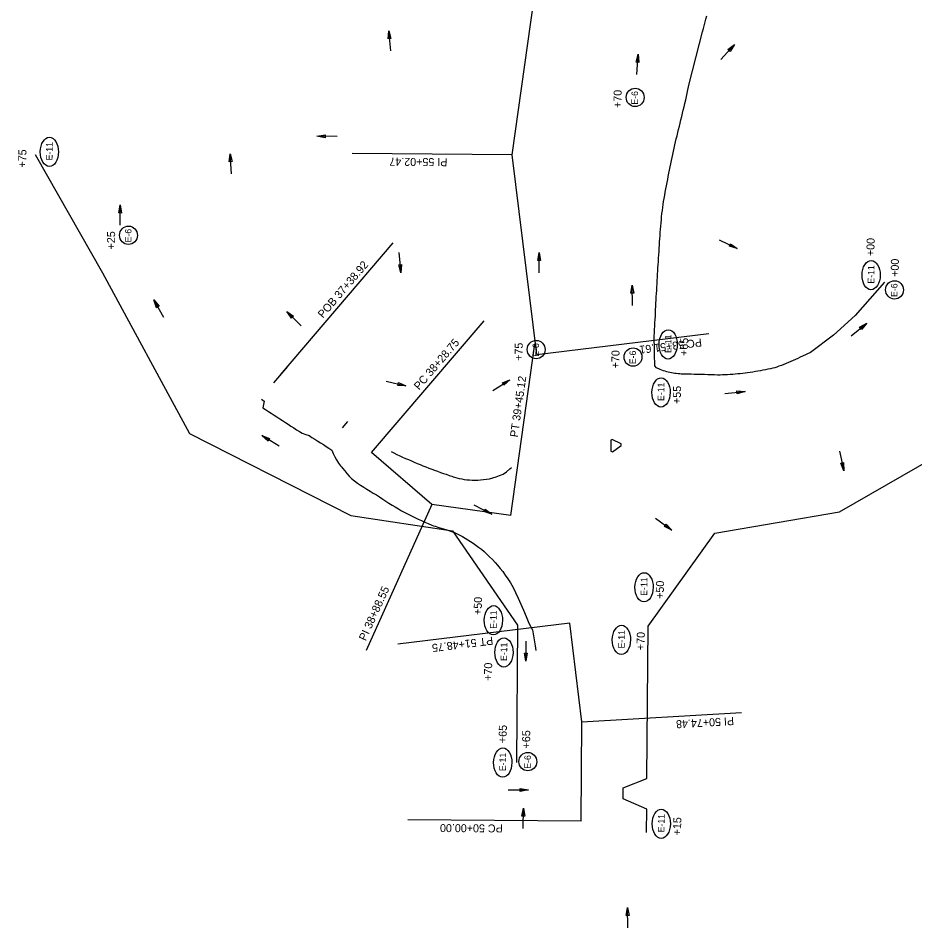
# Model space of a CAD drawing. Extents: x 1312891 to 1314734, y 2088044 to 2090982.
# Drawn here: x 1313567 to 1314240, y 2088044 to 2088726 of the extents above; entities that cross this region are included whole.
import ezdxf

# ---------------------------------------------------------------- set-up
doc = ezdxf.new("R2010")
doc.units = 0
for name, color, linetype in [('43', 7, 'Continuous'), ('44', 7, 'Continuous'), ('Level 1', 7, 'Continuous'), ('Level 44', 7, 'Continuous'), ('R_Horz Alg Annot_Detour', 7, 'Continuous'), ('R_Horz Alg Stationing_Detour', 7, 'Continuous'), ('R_Proposed Const Limits', 7, 'Continuous'), ('R_Proposed Road', 7, 'Continuous')]:
    doc.layers.add(name, color=color, linetype=linetype)

msp = doc.modelspace()

# ---------------------------------------------------------------- linework, layer by layer
at = {"layer": '43'}
for p, q in [((1313844.54, 2088710.17), (1313844.96, 2088716.32)), ((1313844.96, 2088716.32), (1313846.68, 2088710.4)), ((1313846.68, 2088710.4), (1313844.54, 2088710.17)), ((1314099.44, 2088702.13), (1314104.37, 2088705.84)), ((1314101.01, 2088700.67), (1314099.44, 2088702.13)), ((1314104.37, 2088705.84), (1314101.01, 2088700.67)), ((1314030.55, 2088692.66), (1314032.03, 2088698.65)), ((1314032.03, 2088698.65), (1314032.69, 2088692.51)), ((1314032.69, 2088692.51), (1314030.55, 2088692.66)), ((1313791.13, 2088637.22), (1313797.22, 2088638.24)), ((1313797.2, 2088636.1), (1313791.13, 2088637.22)), ((1313797.22, 2088638.24), (1313797.2, 2088636.1)), ((1313725.37, 2088617.96), (1313725.96, 2088624.1)), ((1313725.96, 2088624.1), (1313727.51, 2088618.13)), ((1313727.51, 2088618.13), (1313725.37, 2088617.96)), ((1313642.43, 2088579.66), (1313643.56, 2088585.72)), ((1313643.56, 2088585.72), (1313644.58, 2088579.64)), ((1313644.58, 2088579.64), (1313642.43, 2088579.66)), ((1314100.5, 2088554.7), (1314101.44, 2088556.63)), ((1314106.44, 2088553.02), (1314100.5, 2088554.7)), ((1314101.44, 2088556.63), (1314106.44, 2088553.02)), ((1313956.79, 2088543.99), (1313957.89, 2088550.06)), ((1313958.94, 2088543.98), (1313956.79, 2088543.99)), ((1313957.89, 2088550.06), (1313958.94, 2088543.98)), ((1313852.45, 2088540.8), (1313854.58, 2088541.03)), ((1313854.15, 2088534.87), (1313852.45, 2088540.8)), ((1313854.58, 2088541.03), (1313854.15, 2088534.87)), ((1314026.65, 2088519.5), (1314027.71, 2088525.57)), ((1314027.71, 2088525.57), (1314028.8, 2088519.5)), ((1314028.8, 2088519.5), (1314026.65, 2088519.5)), ((1313668.76, 2088514.45), (1313672.69, 2088509.69)), ((1313670.82, 2088508.63), (1313668.76, 2088514.45)), ((1313672.69, 2088509.69), (1313670.82, 2088508.63)), ((1313768.49, 2088505.76), (1313773.58, 2088502.28)), ((1313772.08, 2088500.74), (1313768.49, 2088505.76)), ((1313773.58, 2088502.28), (1313772.08, 2088500.74)), ((1314198.21, 2088494.08), (1314203.6, 2088497.08)), ((1314203.6, 2088497.08), (1314199.57, 2088492.41)), ((1314199.57, 2088492.41), (1314198.21, 2088494.08)), ((1313851.74, 2088450.37), (1313852.22, 2088452.46)), ((1313857.9, 2088450.05), (1313851.74, 2088450.37)), ((1313852.22, 2088452.46), (1313857.9, 2088450.05)), ((1313930.23, 2088452.33), (1313935.95, 2088454.65)), ((1313931.37, 2088450.51), (1313930.23, 2088452.33)), ((1313935.95, 2088454.65), (1313931.37, 2088450.51)), ((1314106.41, 2088444.08), (1314106.19, 2088446.22)), ((1314106.19, 2088446.22), (1314112.34, 2088445.77)), ((1314112.34, 2088445.77), (1314106.41, 2088444.08)), ((1313749.84, 2088412.78), (1313755.57, 2088410.48)), ((1313754.44, 2088408.66), (1313749.84, 2088412.78)), ((1313755.57, 2088410.48), (1313754.44, 2088408.66)), ((1314184.04, 2088392.04), (1314186.13, 2088392.52)), ((1314186.46, 2088386.36), (1314184.04, 2088392.04)), ((1314186.13, 2088392.52), (1314186.46, 2088386.36)), ((1313916.37, 2088355.83), (1313917.36, 2088357.73)), ((1313922.26, 2088353.98), (1313916.37, 2088355.83)), ((1313917.36, 2088357.73), (1313922.26, 2088353.98)), ((1314051.87, 2088344.67), (1314053.14, 2088346.4)), ((1314053.14, 2088346.4), (1314057.4, 2088341.93)), ((1314057.4, 2088341.93), (1314051.87, 2088344.67)), ((1313947.77, 2088243.59), (1313946.72, 2088249.67)), ((1313946.72, 2088249.67), (1313948.87, 2088249.66)), ((1313948.87, 2088249.66), (1313947.77, 2088243.59)), ((1313943.69, 2088146.06), (1313943.69, 2088148.2)), ((1313943.69, 2088148.2), (1313949.76, 2088147.11)), ((1313949.76, 2088147.11), (1313943.69, 2088146.06)), ((1313944.89, 2088127.46), (1313946.01, 2088133.52)), ((1313946.01, 2088133.52), (1313947.03, 2088127.44)), ((1313947.03, 2088127.44), (1313944.89, 2088127.46)), ((1314023.16, 2088052.89), (1314024.22, 2088058.97)), ((1314024.22, 2088058.97), (1314025.31, 2088052.89)), ((1314025.31, 2088052.89), (1314023.16, 2088052.89))]:
    msp.add_line(p, q, dxfattribs=at)
for points in [[(1313846.58, 2088701.22), (1313844.96, 2088716.32)], [(1314094, 2088694.74), (1314104.37, 2088705.84)], [(1314030.99, 2088683.49), (1314032.03, 2088698.65)], [(1313806.32, 2088637.09), (1313791.13, 2088637.22)], [(1313727.17, 2088608.96), (1313725.96, 2088624.1)], [(1313643.43, 2088570.53), (1313643.56, 2088585.72)], [(1314092.77, 2088559.63), (1314106.44, 2088553.02)], [(1313852.56, 2088549.98), (1313854.15, 2088534.87)], [(1313957.81, 2088534.87), (1313957.89, 2088550.06)], [(1314027.75, 2088510.39), (1314027.71, 2088525.57)], [(1313676.24, 2088501.23), (1313668.76, 2088514.45)], [(1313779.35, 2088495.14), (1313768.49, 2088505.76)], [(1314191.83, 2088487.48), (1314203.6, 2088497.08)], [(1313843.1, 2088453.46), (1313857.9, 2088450.05)], [(1313923.08, 2088446.58), (1313935.95, 2088454.65)], [(1314097.23, 2088444.22), (1314112.34, 2088445.77)], [(1313762.75, 2088404.77), (1313749.84, 2088412.78)], [(1314183.02, 2088401.16), (1314186.46, 2088386.36)], [(1313908.78, 2088360.98), (1313922.26, 2088353.98)], [(1314045.17, 2088350.94), (1314057.4, 2088341.93)], [(1313947.82, 2088258.78), (1313947.77, 2088243.59)], [(1313934.58, 2088147.16), (1313949.76, 2088147.11)], [(1313945.88, 2088118.33), (1313946.01, 2088133.52)], [(1314024.26, 2088043.78), (1314024.22, 2088058.97)]]:
    msp.add_lwpolyline(points, dxfattribs=at)
at = {"layer": 'Level 1'}
for centre, major_axis, ratio in [((1314029.82, 2088666.31), (-0.05, -6.88), 0.97521), ((1313590.41, 2088625.46), (0.1, 10.96), 0.622952), ((1313649.76, 2088562.93), (-0.05, -6.88), 0.97521), ((1314206.86, 2088533.08), (0.1, 10.96), 0.622952), ((1314224.38, 2088522.03), (-0.05, -6.88), 0.97521), ((1314054.62, 2088481.15), (0.1, 10.96), 0.622952), ((1313955.62, 2088477.26), (-0.05, -6.88), 0.97521), ((1314028.25, 2088471.64), (-0.05, -6.88), 0.97521), ((1314049.28, 2088445.12), (0.1, 10.96), 0.622952), ((1314036.53, 2088299.05), (0.1, 10.96), 0.622952), ((1313923.53, 2088274.32), (0.1, 10.96), 0.622952), ((1314019.54, 2088259.61), (0.1, 10.96), 0.622952), ((1313931.43, 2088250.21), (0.1, 10.96), 0.622952), ((1313930.52, 2088167.62), (0.1, 10.96), 0.622952), ((1313949.37, 2088168.37), (-0.05, -6.88), 0.97521), ((1314049.47, 2088121.73), (0.1, 10.96), 0.622952)]:
    msp.add_ellipse(centre, major_axis=major_axis, ratio=ratio, dxfattribs=at)
at = {"layer": 'Level 44'}
for points in [[(1314044.05, 2088484.84), (1314044.18, 2088487.34), (1314044.31, 2088489.83), (1314044.45, 2088492.33), (1314044.58, 2088494.82), (1314044.72, 2088497.32), (1314044.85, 2088499.83), (1314044.99, 2088502.46), (1314045.06, 2088505.03), (1314045.14, 2088507.34), (1314045.26, 2088509.63), (1314045.4, 2088512.02), (1314045.54, 2088514.42), (1314045.69, 2088516.83), (1314045.84, 2088519.23), (1314046, 2088521.63), (1314046.17, 2088524.13), (1314046.3, 2088526.66), (1314046.4, 2088529.11), (1314046.51, 2088531.51), (1314046.63, 2088533.9), (1314046.75, 2088536.2), (1314046.91, 2088538.51), (1314047.09, 2088540.91), (1314047.27, 2088543.31), (1314047.46, 2088545.73), (1314047.65, 2088548.26), (1314047.79, 2088550.78), (1314047.92, 2088553.18), (1314048.06, 2088555.58), (1314048.21, 2088557.98), (1314048.35, 2088560.38), (1314048.5, 2088562.78), (1314048.65, 2088565.11), (1314048.84, 2088567.41), (1314049.05, 2088569.77), (1314049.26, 2088572.15), (1314049.49, 2088574.53), (1314049.65, 2088576.15), (1314049.72, 2088576.83), (1314049.98, 2088579.23), (1314050.25, 2088581.62), (1314050.5, 2088583.9), (1314050.78, 2088585.97), (1314051.17, 2088588.14), (1314051.61, 2088590.51), (1314052.07, 2088592.96), (1314052.47, 2088595.35), (1314052.91, 2088597.66), (1314053.35, 2088600.02), (1314053.81, 2088602.39), (1314054.27, 2088604.75), (1314054.73, 2088607.12), (1314055.2, 2088609.48), (1314055.68, 2088611.84), (1314056.16, 2088614.2), (1314056.65, 2088616.55), (1314057.14, 2088618.91), (1314057.64, 2088621.26), (1314058.14, 2088623.61), (1314058.65, 2088625.97), (1314059.16, 2088628.31), (1314059.68, 2088630.66), (1314060.2, 2088632.97), (1314060.73, 2088635.23), (1314061.3, 2088637.53), (1314061.9, 2088639.94), (1314062.46, 2088642.34), (1314063.02, 2088644.69), (1314063.6, 2088647.08), (1314064.18, 2088649.54), (1314064.76, 2088651.99), (1314065.33, 2088654.36), (1314065.93, 2088656.73), (1314066.56, 2088659.16), (1314067.22, 2088661.75), (1314067.83, 2088664.45), (1314068.35, 2088667.01), (1314068.85, 2088669.47), (1314069.35, 2088671.92), (1314069.83, 2088674.29), (1314070.32, 2088676.49), (1314080.43, 2088715.42), (1314081.07, 2088717.84), (1314082.98, 2088725.07), (1314083.64, 2088727.39)], [(1313579.68, 2088623.4), (1313630.18, 2088534.77), (1313695.42, 2088414.4), (1313816.45, 2088352.89), (1313892.77, 2088341.33), (1313941.6, 2088270.63)], [(1314216.93, 2088527.81), (1314194.89, 2088502.8), (1314178.67, 2088487.98), (1314161.35, 2088475.05)], [(1314044.71, 2088465.07), (1314044.68, 2088465.78), (1314044.57, 2088468.29), (1314044.46, 2088470.8), (1314044.36, 2088473.24), (1314044.28, 2088475.55), (1314044.27, 2088477.95), (1314044.24, 2088480.66), (1314044.12, 2088483.21), (1314044.05, 2088484.84)], [(1314161.35, 2088475.05), (1314155.45, 2088472.26), (1314153.71, 2088471.46), (1314151.88, 2088470.64), (1314150.08, 2088469.82), (1314148.35, 2088469.05), (1314146.61, 2088468.29), (1314144.85, 2088467.55), (1314143.08, 2088466.83), (1314141.31, 2088466.12), (1314139.52, 2088465.43), (1314137.74, 2088464.77), (1314136.05, 2088464.15), (1314134.6, 2088463.68), (1314133.11, 2088463.3), (1314131.33, 2088462.9), (1314129.45, 2088462.49), (1314127.57, 2088462.1), (1314125.69, 2088461.73), (1314123.81, 2088461.38), (1314121.92, 2088461.04), (1314120.04, 2088460.72), (1314118.1, 2088460.41), (1314116.15, 2088460.1), (1314114.24, 2088459.81), (1314112.42, 2088459.55), (1314110.61, 2088459.33), (1314108.74, 2088459.13), (1314106.85, 2088458.95), (1314104.95, 2088458.79), (1314103.04, 2088458.64), (1314101.14, 2088458.52), (1314099.23, 2088458.41), (1314097.32, 2088458.32), (1314095.41, 2088458.24), (1314093.51, 2088458.19), (1314091.56, 2088458.16), (1314089.34, 2088458.22), (1314086.9, 2088458.31), (1314084.39, 2088458.4), (1314081.88, 2088458.49), (1314079.37, 2088458.58), (1314076.62, 2088458.68), (1314074.07, 2088458.64), (1314071.76, 2088458.7), (1314069.23, 2088458.76), (1314066.86, 2088458.8), (1314065.57, 2088458.81), (1314064.48, 2088458.86), (1314063.32, 2088458.95), (1314062, 2088459.08), (1314060.73, 2088459.2), (1314059.59, 2088459.35), (1314058.31, 2088459.56), (1314057.03, 2088459.77), (1314055.87, 2088460), (1314054.69, 2088460.28), (1314053.49, 2088460.6), (1314052.28, 2088460.97), (1314051.05, 2088461.38), (1314049.81, 2088461.85), (1314048.54, 2088462.38), (1314045.97, 2088463.54)], [(1314039.59, 2088269.85), (1314089.53, 2088339.75), (1314183.09, 2088355.58), (1314300.77, 2088423.05), (1314312.71, 2088465.89)], [(1314045.97, 2088463.54), (1314044.71, 2088465.07)], [(1313941.6, 2088270.63), (1313940.78, 2088167.59)], [(1314038.36, 2088115.33), (1314038.5, 2088132.66), (1314020.79, 2088140.53), (1314020.9, 2088148.61), (1314038.68, 2088155.68), (1314039.59, 2088269.85)]]:
    msp.add_lwpolyline(points, dxfattribs=at)
at = {"layer": 'R_Horz Alg Annot_Detour'}
for points in [[(1313956.03, 2088473.54), (1313937.64, 2088623.28), (1313958.64, 2088772.67)], [(1313937.64, 2088623.28), (1313817.65, 2088624.33)], [(1313763.74, 2088458.44), (1313848.31, 2088557.17)], [(1313831.96, 2088400), (1313916.53, 2088498.73)], [(1313956.03, 2088473.54), (1314085.06, 2088489.38)], [(1313936.6, 2088352.77), (1313954.7, 2088481.51)], [(1313936.6, 2088352.77), (1313877.38, 2088361.1), (1313831.96, 2088400)], [(1313877.38, 2088361.1), (1313828.01, 2088251.72)], [(1313980.75, 2088272.19), (1313851.72, 2088256.35)], [(1313989.26, 2088123.79), (1313989.83, 2088198.27), (1313980.75, 2088272.19)], [(1313989.83, 2088198.27), (1314109.63, 2088205.14)], [(1313989.26, 2088123.79), (1313859.26, 2088124.78)]]:
    msp.add_lwpolyline(points, dxfattribs=at)
at = {"layer": 'R_Horz Alg Stationing_Detour'}
for points in [[(1313768.94, 2088464.52), (1313758.53, 2088452.37)], [(1313768.94, 2088464.52), (1313758.53, 2088452.37)], [(1313814.03, 2088423.26), (1313810.13, 2088418.71)]]:
    msp.add_lwpolyline(points, dxfattribs=at)
at = {"layer": 'R_Proposed Const Limits'}
for points in [[(1313749.43, 2088440.08), (1313751.53, 2088438.69), (1313750.54, 2088433.69), (1313752.65, 2088432.31), (1313754.77, 2088430.94), (1313756.89, 2088429.57), (1313759.01, 2088428.2), (1313761.13, 2088426.83), (1313763.23, 2088425.45), (1313765.33, 2088424.06), (1313767.43, 2088422.66), (1313769.53, 2088421.27), (1313771.63, 2088419.88), (1313773.75, 2088418.51), (1313775.87, 2088417.14), (1313777.99, 2088415.77), (1313780.18, 2088414.49), (1313782.7, 2088413.59), (1313785.29, 2088412.77), (1313787.43, 2088411.42), (1313789.56, 2088410.07), (1313791.69, 2088408.71), (1313793.81, 2088407.35), (1313795.94, 2088405.98), (1313798.06, 2088404.62), (1313800.18, 2088403.25), (1313802.2, 2088401.77)], [(1313802.2, 2088401.77), (1313803.43, 2088399.36), (1313804.68, 2088396.97), (1313805.93, 2088394.59), (1313807.19, 2088392.21), (1313808.74, 2088390.18), (1313809.82, 2088389.05), (1313809.79, 2088389), (1313810.4, 2088388.28), (1313811.99, 2088386.3), (1313813.58, 2088384.31), (1313815.28, 2088382.45), (1313817.13, 2088380.54), (1313819.29, 2088378.75), (1313821.51, 2088377.05), (1313823.86, 2088375.51), (1313826.22, 2088374.01), (1313828.61, 2088372.53), (1313831.01, 2088371.09), (1313833.42, 2088369.69), (1313835.85, 2088368.31), (1313838.16, 2088366.76), (1313840.46, 2088365.21), (1313842.78, 2088363.68), (1313845.12, 2088362.18), (1313847.48, 2088360.71), (1313849.85, 2088359.26), (1313852.24, 2088357.84), (1313854.67, 2088356.49), (1313857.1, 2088355.14), (1313859.55, 2088353.82), (1313862.01, 2088352.53), (1313864.49, 2088351.28), (1313867.03, 2088350.14), (1313869.57, 2088349.02), (1313872.13, 2088347.93), (1313874.68, 2088346.82), (1313877.23, 2088345.74), (1313878.69, 2088345.19), (1313879.85, 2088344.79), (1313882.48, 2088343.91), (1313885.13, 2088343.07), (1313887.78, 2088342.26), (1313890.04, 2088341.58), (1313892.15, 2088340.89), (1313894.21, 2088340.03), (1313896.25, 2088339.09), (1313898.28, 2088338.09), (1313900.3, 2088337.03), (1313902.3, 2088335.89), (1313904.31, 2088334.69), (1313906.31, 2088333.41), (1313908.34, 2088332.08), (1313910.38, 2088330.69), (1313912.44, 2088329.2), (1313914.49, 2088327.59), (1313916.54, 2088325.84), (1313918.61, 2088323.97), (1313920.7, 2088321.97), (1313922.81, 2088319.8), (1313924.75, 2088317.73), (1313926.68, 2088315.55), (1313928.61, 2088313.24), (1313930.53, 2088310.78), (1313932.45, 2088308.15), (1313934.38, 2088305.32), (1313936.3, 2088302.28), (1313938.23, 2088298.96), (1313940.18, 2088295.24), (1313942.21, 2088290.98), (1313944.12, 2088286.52), (1313946.04, 2088281.89), (1313947.98, 2088277.09), (1313950.03, 2088272.11), (1313952.72, 2088267.09)], [(1313846.73, 2088400.79), (1313848.9, 2088399.73), (1313851.08, 2088398.69), (1313853.26, 2088397.67), (1313855.44, 2088396.67), (1313857.62, 2088395.69), (1313859.8, 2088394.73), (1313861.99, 2088393.79), (1313864.14, 2088392.82), (1313866.31, 2088391.88), (1313868.49, 2088390.98), (1313870.67, 2088390.11), (1313872.85, 2088389.25), (1313875.04, 2088388.41), (1313877.22, 2088387.59), (1313879.41, 2088386.78), (1313881.6, 2088386), (1313883.79, 2088385.23), (1313885.98, 2088384.48), (1313888.17, 2088383.74), (1313890.35, 2088382.98), (1313892.41, 2088382.27), (1313893.42, 2088381.94), (1313894.23, 2088381.7), (1313896.06, 2088381.18), (1313897.91, 2088380.72), (1313899.79, 2088380.31), (1313901.69, 2088379.96), (1313903.62, 2088379.67), (1313905.58, 2088379.49), (1313907.59, 2088379.39), (1313909.62, 2088379.36), (1313911.71, 2088379.42), (1313913.84, 2088379.56), (1313916.02, 2088379.78), (1313918.28, 2088380.07), (1313920.62, 2088380.48), (1313923.01, 2088381.07), (1313925.48, 2088381.83), (1313928.04, 2088382.77), (1313930.72, 2088383.91), (1313933.22, 2088385.66), (1313935.78, 2088387.73), (1313937.06, 2088388.87)], [(1313952.72, 2088267.09), (1313954.87, 2088255.27), (1313955.43, 2088251.74)]]:
    msp.add_lwpolyline(points, dxfattribs=at)
at = {"layer": 'R_Proposed Road'}
msp.add_lwpolyline([(1314019.31, 2088405.45), (1314019.33, 2088406.7), (1314012.72, 2088409.88), (1314011.68, 2088409.26), (1314011.54, 2088401.15), (1314012.84, 2088400.59)], close=True, dxfattribs=at)

# ---------------------------------------------------------------- texts
at = {"layer": '44'}
for s, rotation, p in [('+70', 89.5, (1314019.6, 2088658.35)), ('+75', 88.324, (1313572.87, 2088613.65)), ('+25', 89.5, (1313639.63, 2088552.32)), ('+00', 88.324, (1314209.19, 2088547.22)), ('+00', 89.5, (1314227.57, 2088531.75)), ('+65', 88.324, (1314069.29, 2088472.4)), ('+75', 89.5, (1313945.39, 2088468.78)), ('+70', 89.5, (1314018.02, 2088463.16)), ('+55', 88.324, (1314063.95, 2088436.37)), ('+50', 88.324, (1314051.19, 2088290.31)), ('+50', 88.324, (1313914.63, 2088278.2)), ('+70', 88.324, (1314036.75, 2088251.88)), ('+70', 88.324, (1313922.29, 2088228.86)), ('+65', 88.324, (1313933.27, 2088182.19)), ('+65', 89.5, (1313951.04, 2088178.25)), ('+15', 88.324, (1314064.13, 2088112.99))]:
    msp.add_text(s, height=6, rotation=rotation, dxfattribs=at).set_placement(p)
at = {"layer": 'Level 1'}
for s, rotation, p in [('E-6 ', 89.55802, (1314031.91, 2088660.87)), ('E-11 ', 89.5, (1313592.75, 2088619.04)), ('E-6 ', 89.55802, (1313651.94, 2088557.59)), ('E-11 ', 89.5, (1314209.2, 2088526.67)), ('E-6 ', 89.55802, (1314226.55, 2088516.69)), ('E-11 ', 89.5, (1314056.96, 2088474.73)), ('E-6 ', 89.55802, (1313957.7, 2088471.82)), ('E-6 ', 89.55802, (1314030.43, 2088466.3)), ('E-11 ', 89.5, (1314051.62, 2088438.7)), ('E-11 ', 89.5, (1314038.87, 2088292.64)), ('E-11 ', 89.5, (1313925.87, 2088267.91)), ('E-11 ', 89.5, (1314021.89, 2088253.2)), ('E-11 ', 89.5, (1313933.77, 2088243.8)), ('E-11 ', 89.5, (1313932.86, 2088161.2)), ('E-6 ', 89.55802, (1313951.55, 2088163.03)), ('E-11 ', 89.5, (1314051.81, 2088115.32))]:
    msp.add_text(s, height=4.876, rotation=rotation, dxfattribs=at).set_placement(p)
at = {"layer": 'R_Horz Alg Annot_Detour'}
for s, rotation, p in [('PI 55+02.47', 179.5, (1313889.02, 2088620.7)), ('POB 37+38.92', 49.41667, (1313795.7, 2088500.37)), ('PC 38+28.75', 49.41667, (1313867.82, 2088446.48)), ('PC 53+51.61', 187, (1314079.47, 2088485.67)), ('PT 39+45.12', 82, (1313941.79, 2088411.25)), ('PI 38+88.55', 65.70833, (1313827.75, 2088258.42)), ('PT 51+48.75', 187, (1313922.93, 2088262.07)), ('PI 50+74.48', 183.28125, (1314103.81, 2088201.8)), ('PC 50+00.00', 179.5625, (1313930.53, 2088121.24))]:
    msp.add_text(s, height=6, rotation=rotation, dxfattribs=at).set_placement(p)

doc.saveas('drawing.dxf')
